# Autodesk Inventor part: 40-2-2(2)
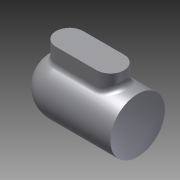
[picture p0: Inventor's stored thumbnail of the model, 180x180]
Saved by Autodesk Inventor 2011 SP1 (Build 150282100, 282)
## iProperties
Created: 2014-01
Part Number: 40-2-2(2)
Document SubType Name: Modeling
Designer: Administrator
Density: 1 g/cm^3
Author: Administrator
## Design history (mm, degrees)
sketch "草图1"
  geometry: L1 (0, 10)-(25, 10); L2 (25, 10)-(25, 0); L3 (25, 0)-(-10, 0); A1 r 10 centre (0, 0) between (0, 10) and (-10, 0); 1 further point
  constraints: 6 end point, 2 point on circle, 1 centre point, 1 coincident, 1 horizontal, 1 parallel, 1 perpendicular, 1 tangent
  dimensions: "d0" = 20 diameter of A1; "d1" = 25 distance of L1.start L1.end; "d2" = 10 distance of L1.end L2.end
revolve "旋转1" sketch "草图1" stored, may be unused: angle "d3" = 90 deg
node "工作平面1"
sketch "草图2"
  geometry: L1 (0, 5)-(15, 5); L2 (15, -5)-(0, -5); A1 r 5 centre (0, 0) between (0, 5) and (0, -5); A2 r 5 centre (15, 0) between (15, -5) and (15, 5); 3 further points
  constraints: 4 end point, 4 point on circle, 2 centre point, 1 coincident, 1 horizontal alignment, 1 tangent
  dimensions: "d5" = 10 diameter of A1; "d6" = 15 distance of L1.start L1.end
extrude "拉伸1" join sketch "草图2" stored distance "d7" = 10; taper "d8" = 0 deg
fillet "圆角1" dims "d9" = 2
node "实体1"
other parameters: "d4" = 15
